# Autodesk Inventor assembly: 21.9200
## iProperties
Created: 2008-10
Part Number: 21.9200
Document SubType Name: Assembly
Designer: Administrator
Mass: 23.2111 g
Surface Area: 73.5796 cm^2
Volume: 14.1159 cm^3
Density: 1.64433 g/cm^3
Description: PARALLEL SLIDE ELEMENT
Author: Administrator
